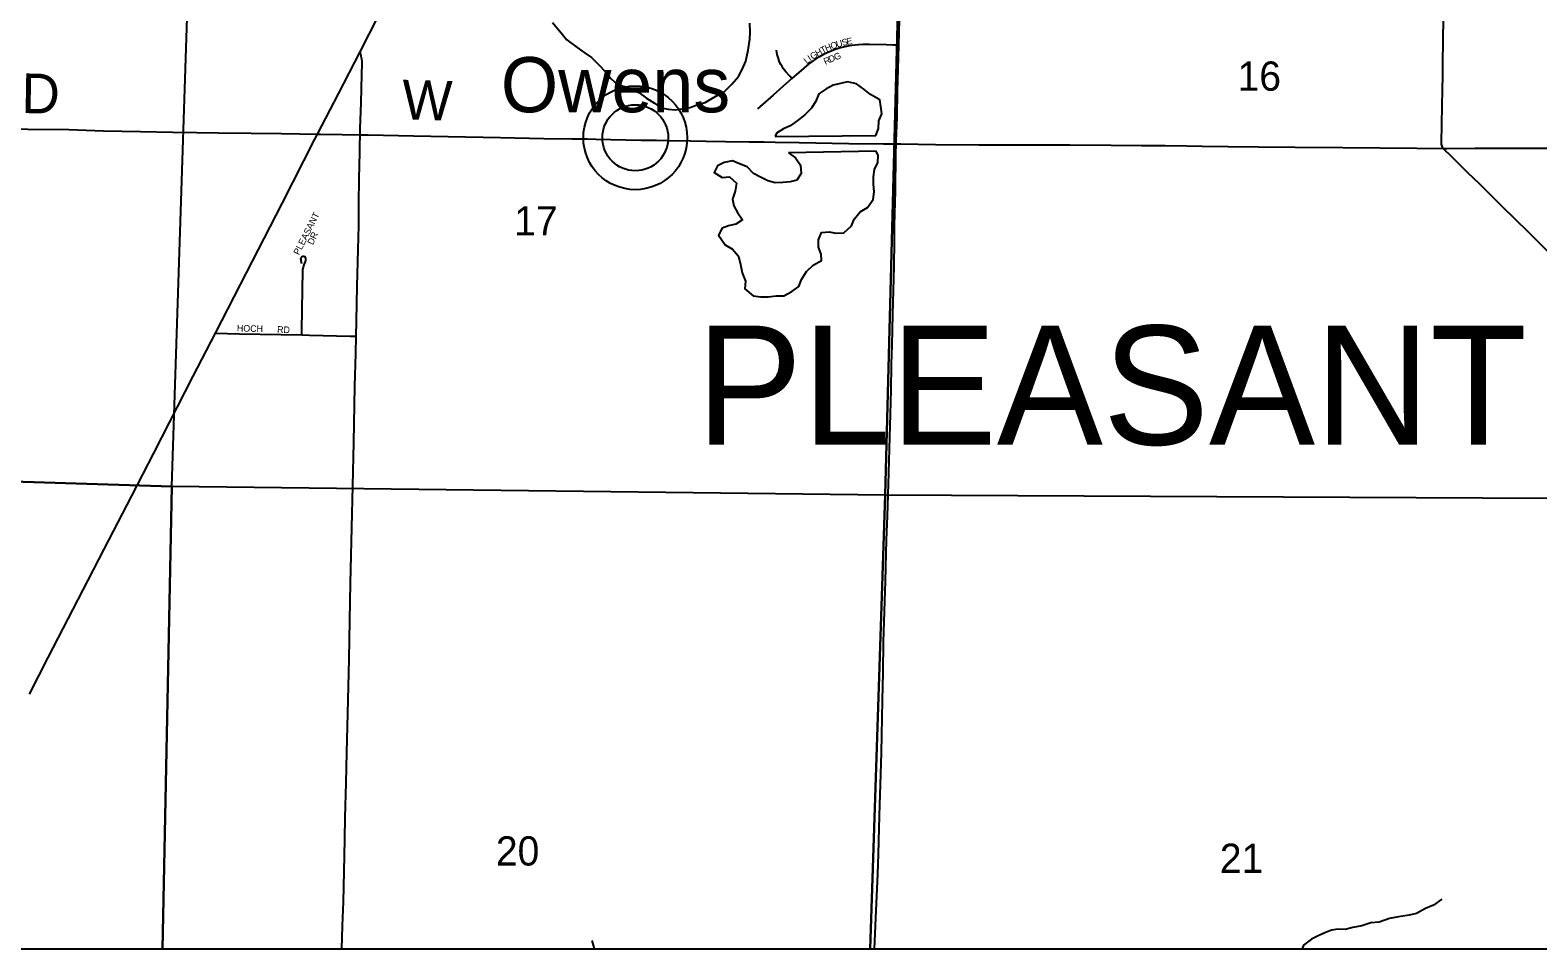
# Model space of a CAD drawing. Extents: x -9.1 to 34, y -3.1 to 22.
# Drawn here: x 2.915 to 5.075, y 14.1 to 15.416 of the extents above; entities that cross this region are included whole.
import ezdxf

# ---------------------------------------------------------------- set-up
doc = ezdxf.new("R2010")
doc.units = 0
for name, color, linetype in [('GM_X_County_Road', 7, 'Continuous'), ('GM_X_County_Road_Text', 7, 'Continuous'), ('GM_X_Minor_Lake', 7, 'Continuous'), ('GM_X_Minor_River', 7, 'Continuous'), ('GM_X_Section', 7, 'Continuous'), ('GM_X_Section_Text', 7, 'Continuous'), ('GM_X_State_Route', 7, 'Continuous'), ('GM_X_Township', 7, 'Continuous'), ('GM_X_Township_Subdivision', 7, 'Continuous'), ('GM_X_Township_Subdivision_Text', 7, 'Continuous'), ('GM_X_Township_Text', 7, 'Continuous'), ('GM_X_Unincorporated', 7, 'Continuous'), ('GM_X_Unincorporated_Location', 7, 'Continuous'), ('GM_X_Unincorporated_Text', 7, 'Continuous'), ('SH_Data', 7, 'Continuous')]:
    doc.layers.add(name, color=color, linetype=linetype)

msp = doc.modelspace()

# ---------------------------------------------------------------- linework, layer by layer
at = {"layer": 'GM_X_County_Road'}
for points in [[(4.9398, 15.2467), (4.9393, 15.2473), (4.9386, 15.2485), (4.938, 15.2498), (4.9377, 15.2511), (4.9374, 15.2527), (4.9375, 15.254), (4.9377, 15.2819), (4.9388, 15.3316), (4.9392, 15.3503), (4.9393, 15.3689), (4.9397, 15.4), (4.9403, 15.4341), (4.9419, 15.5086), (4.9423, 15.5428), (4.9432, 15.5863), (4.9436, 15.6124), (4.9437, 15.6283)], [(4.1594, 15.3947), (4.1603, 15.4313), (4.1613, 15.4841), (4.1621, 15.5338), (4.1628, 15.5618), (4.1633, 15.5934)], [(3.3875, 15.2661), (3.3877, 15.2748), (3.3891, 15.3122), (3.3901, 15.3524), (3.3906, 15.3684), (3.3905, 15.3717), (3.3901, 15.3743), (3.3897, 15.3765), (3.389, 15.3791), (3.3874, 15.3851)], [(4.1558, 15.253), (4.1559, 15.2574), (4.1571, 15.2915), (4.1579, 15.3288), (4.1586, 15.3598), (4.1594, 15.3947)], [(2.623, 15.2815), (2.6502, 15.2808), (2.7123, 15.2793), (2.7807, 15.2775), (2.8118, 15.2769), (2.8677, 15.2753), (2.9112, 15.2744), (2.9702, 15.2735), (3.0199, 15.272), (3.0727, 15.271), (3.1193, 15.2701), (3.1535, 15.2695), (3.1846, 15.269), (3.2312, 15.2683), (3.2747, 15.2678), (3.3266, 15.267)], [(3.3266, 15.267), (3.3306, 15.2669), (3.3617, 15.2665), (3.3875, 15.2661)], [(3.3818, 14.9777), (3.3824, 14.9993), (3.3835, 15.0492), (3.3847, 15.1017), (3.3855, 15.1362), (3.3857, 15.1543), (3.3859, 15.1728), (3.386, 15.1977), (3.3862, 15.2037), (3.387, 15.2408), (3.3871, 15.2501), (3.3875, 15.2661)], [(3.3875, 15.2661), (3.399, 15.266), (3.4425, 15.2652), (3.4642, 15.2648), (3.5139, 15.2638), (3.5885, 15.2623), (3.6506, 15.261), (3.691, 15.2603), (3.7127, 15.2602), (3.7251, 15.2599), (3.7903, 15.2585), (3.8121, 15.2583), (3.8276, 15.2581), (3.8617, 15.2574), (3.8835, 15.2569), (3.9113, 15.2567), (3.9451, 15.2562), (3.9668, 15.256), (3.9823, 15.2557), (4.0165, 15.2549), (4.0879, 15.2535), (4.1376, 15.2531), (4.1558, 15.253)], [(4.1247, 14.1), (4.1266, 14.144), (4.1294, 14.2073), (4.1303, 14.2354), (4.1313, 14.2727), (4.1324, 14.3068), (4.1332, 14.3348), (4.1345, 14.3814), (4.1363, 14.4559), (4.1372, 14.4963), (4.1378, 14.5398), (4.1391, 14.5833), (4.1403, 14.6268), (4.1421, 14.6858), (4.1433, 14.72), (4.1451, 14.7821), (4.146, 14.8162), (4.1476, 14.8659), (4.1484, 14.9001), (4.1493, 14.9374), (4.15, 14.9653), (4.1512, 15.0088), (4.1528, 15.0772), (4.1533, 15.1144), (4.1536, 15.1362), (4.1546, 15.1859), (4.1555, 15.2387), (4.1558, 15.253)], [(4.1558, 15.253), (4.1625, 15.253), (4.2121, 15.2524), (4.2743, 15.2515), (4.3333, 15.2515), (4.3612, 15.2515), (4.4047, 15.2515), (4.4637, 15.2513), (4.5072, 15.2506), (4.5414, 15.2506), (4.5724, 15.2502), (4.5942, 15.2499), (4.6315, 15.2495), (4.675, 15.249), (4.7278, 15.2486), (4.7961, 15.248), (4.849, 15.2476), (4.9018, 15.2471), (4.9398, 15.2467)], [(4.9398, 15.2467), (4.9453, 15.2466), (4.9857, 15.2469), (5.0975, 15.2469), (5.169, 15.2466), (5.2467, 15.2465), (5.2964, 15.2459), (5.3182, 15.2459), (5.3741, 15.246), (5.4611, 15.2456), (5.5046, 15.2453), (5.5264, 15.2453), (5.545, 15.2454), (5.5885, 15.2459), (5.6165, 15.2459), (5.6911, 15.2461), (5.806, 15.2463), (5.8464, 15.2462), (5.8993, 15.2459), (5.9245, 15.2457)], [(5.106, 15.0826), (5.062, 15.1264), (5.0244, 15.1634), (5.0045, 15.1831), (4.9912, 15.1961), (4.9756, 15.2113), (4.9491, 15.2376), (4.9423, 15.2438), (4.9403, 15.2461), (4.9398, 15.2467)], [(3.3615, 14.1), (3.3624, 14.133), (3.3635, 14.1671), (3.3646, 14.2106), (3.3656, 14.2572), (3.3661, 14.2882), (3.3674, 14.3379), (3.3687, 14.3814), (3.3698, 14.4373), (3.3716, 14.5149), (3.3727, 14.5708), (3.3739, 14.6236), (3.3761, 14.723), (3.377, 14.7633), (3.3784, 14.8254), (3.38, 14.9062), (3.3812, 14.9527), (3.3818, 14.9777)]]:
    msp.add_lwpolyline(points, dxfattribs=at)
at = {"layer": 'GM_X_Minor_Lake'}
for points in [[(4.1265, 15.2649), (4.1305, 15.2751), (4.131, 15.2861), (4.135, 15.2959), (4.134, 15.3065), (4.1323, 15.316), (4.1192, 15.3238), (4.1095, 15.3316), (4.099, 15.3389), (4.0862, 15.3418), (4.076, 15.3397), (4.0657, 15.3372), (4.055, 15.3317), (4.0447, 15.3247), (4.0408, 15.3142), (4.0345, 15.3041), (4.0249, 15.2947), (4.0138, 15.2862), (4.0039, 15.2788), (3.9944, 15.2748), (3.9844, 15.2685), (3.9825, 15.2636)], [(3.9825, 15.2636), (4.1265, 15.2649)], [(4.0013, 15.2402), (4.0114, 15.2332), (4.0188, 15.2224), (4.0198, 15.2107), (4.0132, 15.2009), (4.0037, 15.1988), (3.9931, 15.1979), (3.9825, 15.1973), (3.9716, 15.2001), (3.9615, 15.2056), (3.9513, 15.2107), (3.9424, 15.2204), (3.9312, 15.2247), (3.921, 15.2287), (3.9093, 15.2266), (3.8997, 15.2218), (3.8947, 15.2121), (3.9063, 15.2051), (3.9169, 15.206), (3.9269, 15.1967), (3.9248, 15.1854), (3.9212, 15.1737), (3.9233, 15.1642), (3.9285, 15.1546), (3.9355, 15.1443), (3.9259, 15.138), (3.9157, 15.1355), (3.9062, 15.1323), (3.9011, 15.1225), (3.9107, 15.1087), (3.9212, 15.1025), (3.9297, 15.0921), (3.9329, 15.0803), (3.935, 15.0685), (3.9397, 15.0566), (3.9391, 15.0453), (3.9507, 15.0356), (3.962, 15.0339), (3.9722, 15.0341), (3.9836, 15.0354), (3.9949, 15.0356), (4.006, 15.0415), (4.0163, 15.0489), (4.0203, 15.059), (4.0273, 15.0703), (4.0369, 15.0792), (4.0487, 15.0858), (4.0485, 15.0953), (4.0445, 15.1052), (4.0443, 15.1155), (4.0486, 15.126), (4.0596, 15.127), (4.0694, 15.1253), (4.0807, 15.1258), (4.0919, 15.1355), (4.0954, 15.1453), (4.1043, 15.1558), (4.1146, 15.162), (4.1227, 15.1733), (4.1244, 15.1846), (4.1231, 15.1956), (4.1233, 15.2059), (4.1246, 15.2164), (4.1297, 15.2262), (4.1298, 15.2364), (4.1273, 15.2426)], [(4.1273, 15.2426), (4.0013, 15.2402)]]:
    msp.add_lwpolyline(points, dxfattribs=at)
at = {"layer": 'GM_X_Minor_River'}
for points in [[(3.6631, 15.4268), (3.6731, 15.4149), (3.6838, 15.4022), (3.6984, 15.391), (3.7085, 15.384), (3.719, 15.377), (3.7297, 15.3662), (3.739, 15.3565), (3.7468, 15.3469), (3.7565, 15.338), (3.7663, 15.3352), (3.776, 15.3313), (3.7869, 15.3269), (3.7978, 15.3188), (3.8093, 15.3114), (3.8191, 15.3047), (3.8289, 15.3027), (3.8391, 15.3017), (3.8493, 15.3031), (3.8603, 15.3052), (3.8702, 15.3088), (3.882, 15.3124), (3.8972, 15.3216), (3.9087, 15.3271), (3.9202, 15.3386), (3.9298, 15.3495), (3.9353, 15.3604), (3.9404, 15.3716), (3.9437, 15.3875), (3.9458, 15.403), (3.9464, 15.4132), (3.9458, 15.4261)], [(4.9378, 14.1713), (4.9259, 14.1624), (4.9145, 14.1577), (4.9015, 14.1507), (4.8909, 14.1483), (4.8757, 14.1459), (4.8628, 14.1434), (4.848, 14.1384), (4.8359, 14.1371), (4.823, 14.1331), (4.8101, 14.1307), (4.7994, 14.1275), (4.7892, 14.128), (4.7798, 14.1267), (4.7703, 14.1231), (4.7607, 14.1187), (4.7512, 14.1139), (4.7397, 14.1054), (4.7375, 14.1)], [(3.7195, 14.112), (3.7227, 14.1018), (3.7237, 14.1)]]:
    msp.add_lwpolyline(points, dxfattribs=at)
at = {"layer": 'GM_X_Section'}
for p, q in [((3.1042, 14.1), (4.1187, 14.1)), ((4.1187, 14.1), (5.1778, 14.1))]:
    msp.add_line(p, q, dxfattribs=at)
for points in [[(2.6, 14.7785), (3.1179, 14.7624), (3.1506, 15.7703), (2.6, 15.7826)], [(2.6, 14.7785), (2.6, 14.1), (3.1042, 14.1)], [(3.1042, 14.1), (3.1179, 14.7624), (2.6, 14.7785)], [(4.1187, 14.1), (4.1399, 14.7501), (3.1179, 14.7624), (3.1042, 14.1)], [(5.1778, 14.1), (5.1863, 14.7444), (4.1399, 14.7501), (4.1187, 14.1)]]:
    msp.add_lwpolyline(points, dxfattribs=at)
for points in [[(3.1506, 15.7703), (4.1665, 15.7524), (4.1399, 14.7501), (3.1179, 14.7624)], [(4.1665, 15.7524), (5.2057, 15.7528), (5.1863, 14.7444), (4.1399, 14.7501)]]:
    msp.add_lwpolyline(points, close=True, dxfattribs=at)
at = {"layer": 'GM_X_State_Route'}
msp.add_lwpolyline([(2.9135, 14.4648), (2.9405, 14.5173), (2.9978, 14.6281), (3.0208, 14.6726), (3.0604, 14.7491), (3.0917, 14.8098), (3.1484, 14.9204), (3.1802, 14.982), (3.2159, 15.0516), (3.2756, 15.1676), (3.3223, 15.2588), (3.3266, 15.267), (3.3567, 15.325), (3.3874, 15.3851), (3.4132, 15.4356)], dxfattribs=at)
at = {"layer": 'GM_X_Township'}
msp.add_lwpolyline([(2.6, 15.2819), (2.6, 14.1), (8.1877, 14.1)], dxfattribs=at)
at = {"layer": 'GM_X_Township_Subdivision'}
for points in [[(4.0063, 15.3466), (4.0032, 15.35), (3.9976, 15.3563), (3.9939, 15.3613), (3.9922, 15.3639), (3.9906, 15.3666), (3.9892, 15.3694), (3.9879, 15.3722), (3.9869, 15.3752), (3.986, 15.3782), (3.9854, 15.3812), (3.9844, 15.3874)], [(4.1594, 15.3947), (4.151, 15.3947), (4.1418, 15.395), (4.1171, 15.3955), (4.1078, 15.3955), (4.1016, 15.3951), (4.0924, 15.3941), (4.0863, 15.3931), (4.0802, 15.3918), (4.0743, 15.3902), (4.0684, 15.3883), (4.0626, 15.3861), (4.057, 15.3836), (4.0514, 15.3809), (4.0459, 15.378), (4.0406, 15.3748), (4.0355, 15.3713), (4.0306, 15.3676), (4.0235, 15.3616), (4.0063, 15.3466)], [(4.0063, 15.3466), (3.9933, 15.3351), (3.9793, 15.3229), (3.9608, 15.3065), (3.9572, 15.3033)], [(3.304, 14.9795), (3.3041, 14.987), (3.3043, 15.0146), (3.305, 15.0454), (3.3054, 15.07), (3.3055, 15.073), (3.3057, 15.0745), (3.3063, 15.0771), (3.3068, 15.0785), (3.3073, 15.08), (3.3094, 15.0846), (3.3097, 15.0856), (3.3099, 15.0867), (3.3099, 15.0876), (3.3099, 15.0884), (3.3097, 15.0892), (3.3095, 15.0898), (3.3091, 15.0905), (3.3086, 15.0911), (3.3079, 15.0915), (3.3071, 15.0918), (3.3063, 15.0919), (3.3056, 15.0919), (3.3048, 15.0917), (3.3043, 15.0914), (3.3037, 15.091), (3.3032, 15.0905), (3.3028, 15.0898), (3.3024, 15.0892), (3.3023, 15.0884), (3.3024, 15.0869), (3.3025, 15.0861), (3.3037, 15.0816)], [(3.1802, 14.982), (3.2147, 14.9812), (3.304, 14.9795)], [(3.304, 14.9795), (3.3148, 14.9793), (3.3731, 14.9778), (3.3788, 14.9778), (3.3818, 14.9777)]]:
    msp.add_lwpolyline(points, dxfattribs=at)
at = {"layer": 'GM_X_Unincorporated'}
for radius in [0.0744, 0.0472]:
    msp.add_circle((3.7819, 15.2619), radius, dxfattribs=at)
at = {"layer": 'GM_X_Unincorporated_Location'}
msp.add_line((3.7819, 15.2619), (3.7819, 15.2619), dxfattribs=at)
at = {"layer": 'SH_Data'}
msp.add_line((2.6, 14.1), (9.4, 14.1), dxfattribs=at)

# ---------------------------------------------------------------- texts
at = {"layer": 'GM_X_County_Road_Text'}
for s, height, rotation, p in [('RD', 0.05682, 359.0342, (2.847, 15.2982)), ('W', 0.0568, 358.5554, (3.4472, 15.2882))]:
    msp.add_text(s, height=height, rotation=rotation, dxfattribs=at).set_placement(p)
at = {"layer": 'GM_X_Section_Text'}
for s, p in [('16', (4.645, 15.3293)), ('17', (3.6083, 15.1219)), ('20', (3.5821, 14.2193)), ('21', (4.6196, 14.2088))]:
    msp.add_text(s, height=0.04186, rotation=0, dxfattribs=at).set_placement(p)
at = {"layer": 'GM_X_Township_Subdivision_Text'}
for s, rotation, p in [('G', 33.1687, (4.0362, 15.3733)), ('H', 30.2627, (4.0431, 15.3778)), ('T', 27.4938, (4.0502, 15.382)), ('H', 23.4454, (4.0559, 15.385)), ('O', 19.4994, (4.0634, 15.3882)), ('U', 15.7803, (4.0711, 15.3909)), ('S', 14.3278, (4.0791, 15.3932)), ('E', 10.6348, (4.0854, 15.3948)), ('L', 37.9301, (4.0277, 15.367)), ('I', 34.3689, (4.0328, 15.371)), ('R', 24.5987, (4.0544, 15.3661)), ('D', 24.0712, (4.0612, 15.3692)), ('G', 21.0344, (4.0687, 15.3725)), ('PLEASANT', 63.0739, (3.2998, 15.0931)), ('DR', 64.7982, (3.3199, 15.1076)), ('HOCH', 358.5321, (3.2109, 14.9844)), ('RD', 356.989, (3.2684, 14.9827))]:
    msp.add_text(s, height=0.00947, rotation=rotation, dxfattribs=at).set_placement(p)
at = {"layer": 'GM_X_Township_Text'}
msp.add_text('PLEASANT', height=0.17045, rotation=0, dxfattribs=at).set_placement((3.8692, 14.8222))
at = {"layer": 'GM_X_Unincorporated_Text'}
msp.add_text('Owens', height=0.07898, rotation=0, dxfattribs=at).set_placement((3.5892, 15.2984))

doc.saveas('drawing.dxf')
